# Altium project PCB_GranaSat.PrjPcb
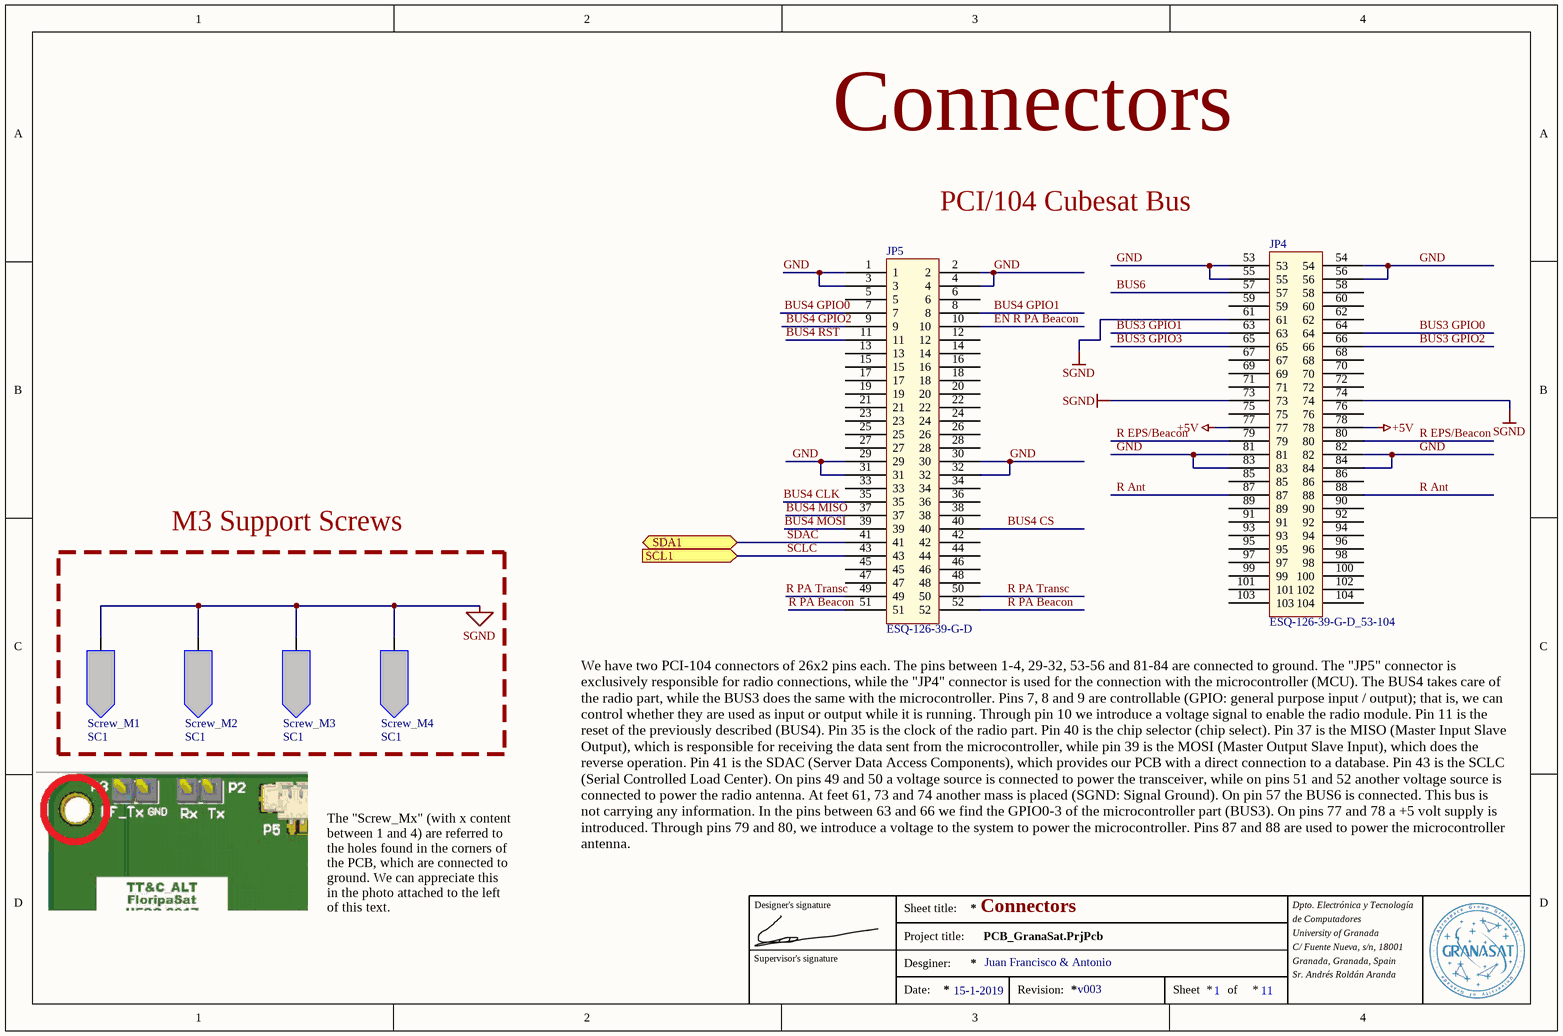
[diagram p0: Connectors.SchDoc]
11 sheets, 61 parts. Net scope: hierarchical (ports join the sheet entries above them; power ports are global).
Board files: PCBGranaSat.PcbDoc, PCBGSat.PCBdoc, PCB1.PcbDoc
Sheets:
  Connectors.SchDoc
  Interface.SchDoc
  Modules.SchDoc
  BeaconMCU.SchDoc
  BeaconMCU_Explained.SchDoc
  DecouplingCapacitors.SchDoc
  PullupResistors.SchDoc
  Reset.SchDoc
  LedsSystem.SchDoc
  Radio_RF4463F30_Beacon.SchDoc
  Radio_RF4463F30_Transceiver.SchDoc

## Sheet Connectors.SchDoc
size A4

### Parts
JP4  ESQ-126-39-G-D_53-104  [ESQ-126-39-G-D_53_104]
JP5  ESQ-126-39-G-D  [ESQ-126-39-G-D]
Screw_M1  SC1  [Screw_M3]
Screw_M2  SC1  [Screw_M3]
Screw_M3  SC1  [Screw_M3]
Screw_M4  SC1  [Screw_M3]

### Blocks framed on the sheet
M3 Support Screws: Screw_M1-Screw_M4

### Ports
SCL1 (in), SDA1 (bidir)

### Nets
+5V: JP4.77 JP4.78
SGND: JP4.61 JP4.73 JP4.74 Screw_M1.1 Screw_M2.1 Screw_M3.1 Screw_M4.1
BUS3 GPIO0: JP4.64
BUS3 GPIO1: JP4.63
BUS3 GPIO2: JP4.66
BUS3 GPIO3: JP4.65
BUS4 CLK: JP5.35
BUS4 CS: JP5.40
BUS4 GPIO0: JP5.7
BUS4 GPIO1: JP5.8
BUS4 GPIO2: JP5.9
BUS4 MISO: JP5.37
BUS4 MOSI: JP5.39
BUS4 RST: JP5.11
BUS6: JP4.57
EN R PA Beacon: JP5.10
GND: JP4.53 JP4.54 JP4.55 JP4.56 JP4.81 JP4.82 JP4.83 JP4.84 JP5.1 JP5.2 JP5.3 JP5.4 JP5.29 JP5.30 JP5.31 JP5.32
R Ant: JP4.87 JP4.88
R EPS/Beacon: JP4.79 JP4.80
R PA Beacon: JP5.51 JP5.52
R PA Transc: JP5.49 JP5.50
SCLC: JP5.43 ; port SCL1
SDAC: JP5.41 ; port SDA1

Not connected (* = marked no-connect by the designer): JP4 58 59 60 62 67 68 69 70 71 72 75 76 85 86 89 90 91 92 93 94 95 96 97 98 99 100 101 102 103 104; JP5 5 6 12 13 14 15 16 17 18 19 20 21 22 23 24 25 26 27 28 33 34 36 38 42 44 45 46 47 48

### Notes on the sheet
- Connectors
- PCI/104 Cubesat Bus
- We have two PCI-104 connectors of 26x2 pins each. The pins between 1-4, 29-32, 53-56 and 81-84 are connected to ground. The "JP5" connector is exclusively responsible for radio connections, while the "JP4" connector is used for the connection with the microcontroller (MCU). The BUS4 takes care of the radio part, while the BUS3 does the same with the microcontroller. Pins 7, 8 and 9 are controllable (GPIO: general purpose input / output); that is, we can control whether they are used as input or output while it is running. Through pin 10 we introduce a voltage signal to enable the radio module. Pin 11 is the reset of the previously described (BUS4). Pin 35 is the clock of the radio part. Pin 40 is the chip selector (chip select). Pin 37 is the MISO (Master Input Slave Output), which is responsible for receiving the data sent from the microcontroller, while pin 39 is the MOSI (Master Output Slave Input), which does the reverse operation. Pin 41 is the SDAC (Server Data Access Components), which provides our PCB with a direct connection to a database. Pin 43 is the SCLC (Serial Controlled Load Center). On pins 49 and 50 a voltage source is connected to power the transceiver, while on pins 51 and 52 another voltage source is connected to power the radio antenna. At feet 61, 73 and 74 another mass is placed (SGND: Signal Ground). On pin 57 the BUS6 is connected. This bus is not carrying any information. In the pins between 63 and 66 we find the GPIO0-3 of the microcontroller part (BUS3). On pins 77 and 78 a +5 volt supply is introduced. Through pins 79 and 80, we introduce a voltage to the system to power the microcontroller. Pins 87 and 88 are used to power the microcontroller antenna.
- The "Screw_Mx" (with x content between 1 and 4) are referred to the holes found in the corners of the PCB, which are connected to ground. We can appreciate this in the photo attached to the left of this text.
- Designer's signature
- Sheet title:
- Dpto. Electrónica y Tecnología
- de Computadores
- Supervisor's signature
- Project title:
- Desginer:
- Juan Francisco & Antonio
- University of Granada
- C/ Fuente Nueva, s/n, 18001
- Granada, Granada, Spain
- Sr. Andrés Roldán Aranda
- Date:
- 15-1-2019
- Revision:
- v003
- Sheet
- 1
- of
- 11

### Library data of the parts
JP4 = ESQ-126-39-G-D_53-104: Cubesat Header Connector; Shop: es.rs-online.com; Localización: Último cajón cajonera blanca entre Pablo y Luis; Reference: 254-6132
JP5 = ESQ-126-39-G-D: Cubesat Header Connector; Shop: es.rs-online.com; Localización: Último cajón cajonera blanca entre Pablo y Luis; Reference: 254-6132
Screw_M1-Screw_M4 = Screw_M3: Main CubeSAT bus

## Sheet Interface.SchDoc
size A4
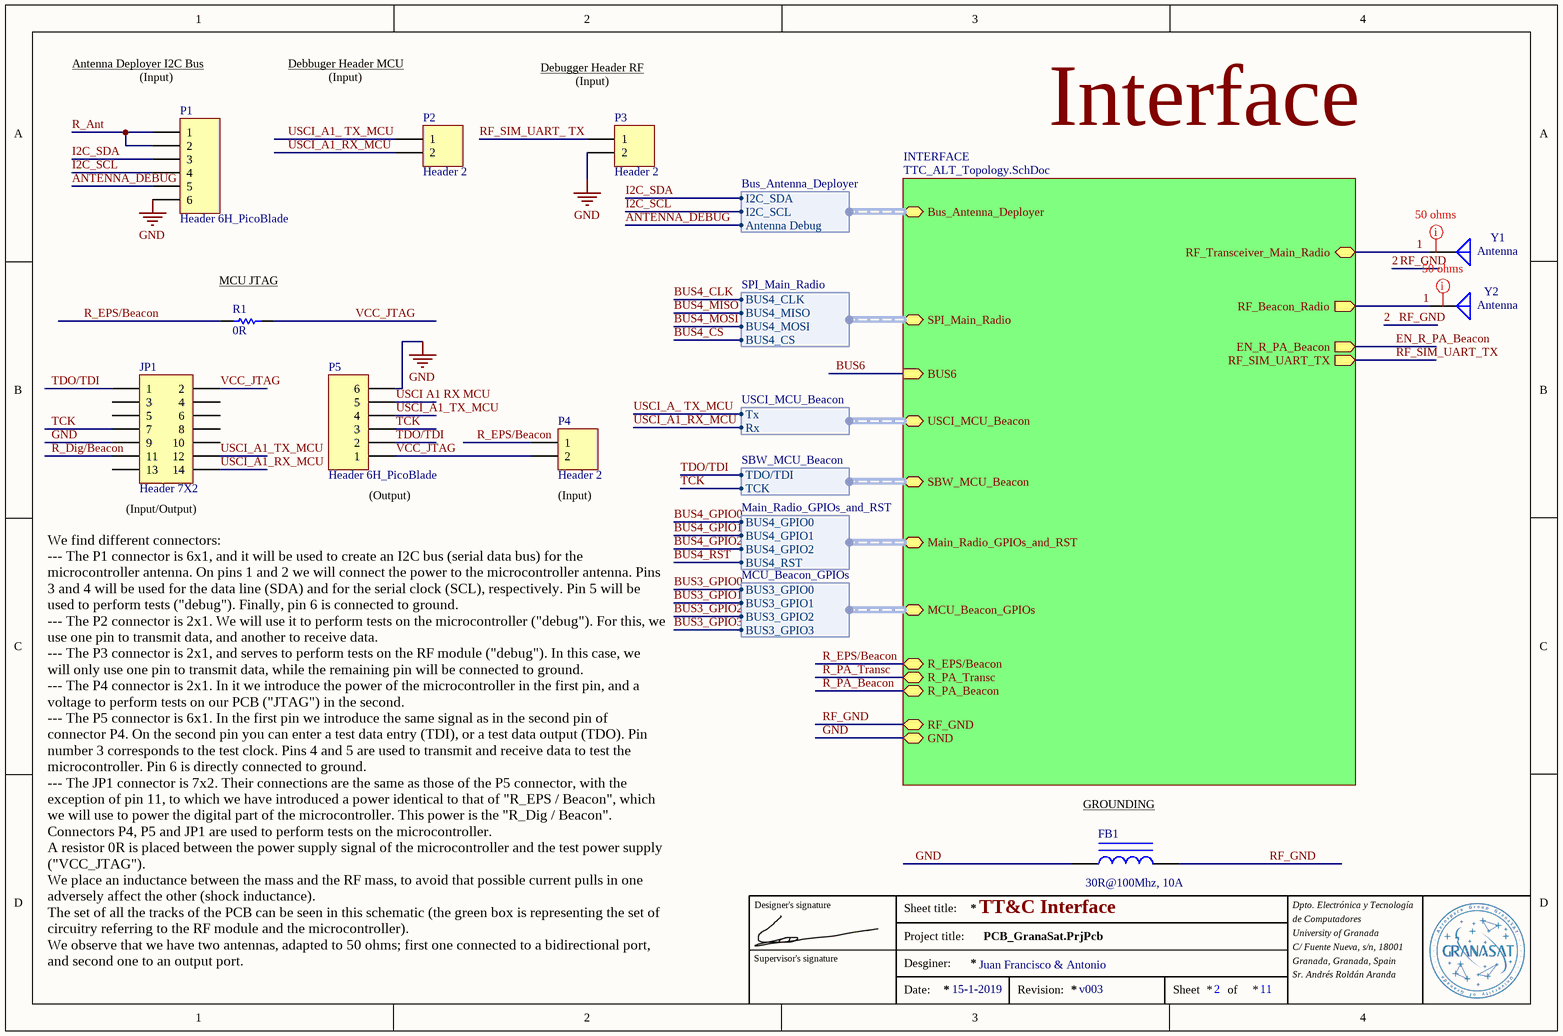
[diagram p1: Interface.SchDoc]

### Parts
FB1  value 30R@100Mhz, 10A  [INDC3216]
JP1  Header 7X2  [HDR2X7]
P1  Header 6H_PicoBlade  [HDR1X6H]
P2  Header 2  [HDR1X2]
P3  Header 2  [HDR1X2]
P4  Header 2  [HDR1X2]
P5  Header 6H_PicoBlade  [HDR1X6H]
R1  0R  [R]
Y1  Antenna  [PIN1]
Y2  Antenna  [PIN1]

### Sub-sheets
INTERFACE = TTC_ALT_Topology.SchDoc (file not in this document): RF_Transceiver_Main_Radio, RF_Beacon_Radio (out), EN_R_PA_Beacon (out), RF_SIM_UART_TX (out), Bus_Antenna_Deployer (harness Bus_Antenna_Deployer), SPI_Main_Radio (harness SPI_Main_Radio), BUS6 (in), Main_Radio_GPIOs_and_RST (harness Main_Radio_GPIOs_and_RST), USCI_MCU_Beacon (harness USCI_MCU_Beacon), MCU_Beacon_GPIOs (harness MCU_Beacon_GPIOs), R_EPS/Beacon, R_PA_Transc, R_PA_Beacon, RF_GND, GND, SBW_MCU_Beacon (harness SBW_MCU_Beacon)

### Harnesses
Bus_Antenna_Deployer: I2C_SDA, I2C_SCL, Antenna Debug
SPI_Main_Radio: BUS4_CLK, BUS4_MISO, BUS4_MOSI, BUS4_CS
SBW_MCU_Beacon: TDO/TDI, TCK
Main_Radio_GPIOs_and_RST: BUS4_GPIO0, BUS4_GPIO1, BUS4_GPIO2, BUS4_RST
MCU_Beacon_GPIOs: BUS3_GPIO0, BUS3_GPIO1, BUS3_GPIO2, BUS3_GPIO3
USCI_MCU_Beacon: Tx, Rx

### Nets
GND: FB1.1 JP1.9 P1.6 P3.2 P5.6 ; sheet INTERFACE/GND
1: Y1.1(A) Y2.1(A) ; sheet INTERFACE/RF_Transceiver_Main_Radio, sheet INTERFACE/RF_Beacon_Radio
2: FB1.2 ; sheet INTERFACE/RF_GND  [also labelled RF_GND]
ANTENNA_DEBUG: P1.5 ; sheet INTERFACE/Bus_Antenna_Deployer.Antenna Debug
I2C_SCL: P1.4 ; sheet INTERFACE/Bus_Antenna_Deployer.I2C_SCL
I2C_SDA: P1.3 ; sheet INTERFACE/Bus_Antenna_Deployer.I2C_SDA
R_Ant: P1.1 P1.2
R_Dig/Beacon: JP1.11
R_EPS/Beacon: P4.1 R1.1 ; sheet INTERFACE/R_EPS/Beacon
RF_SIM_UART_ TX: P3.1
TCK: JP1.7 P5.3 ; sheet INTERFACE/SBW_MCU_Beacon.TCK
TDO/TDI: JP1.1 P5.2 ; sheet INTERFACE/SBW_MCU_Beacon.TDO/TDI
USCI A1 RX MCU: P5.5
USCI_A1_ TX_MCU: P2.1
USCI_A1_RX_MCU: JP1.14 P2.2 ; sheet INTERFACE/USCI_MCU_Beacon.Rx
USCI_A1_TX_MCU: JP1.12 P5.4
VCC_JTAG: JP1.2 P4.2 P5.1 R1.2

Not connected (* = marked no-connect by the designer): JP1 3 4 5 6 8 10 13

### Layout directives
mark named 50 ohms: (no net found under the mark)

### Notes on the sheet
- Antenna Deployer I2C Bus
- (near P1) (Input)
- Debbuger Header MCU
- (Input)
- Debugger Header RF
- (near P3) (Input)
- Interface
- (near R1) MCU JTAG
- (near JP1) (Input/Output)
- (near P5) (Output)
- (near P4) (Input)
- (near FB1) GROUNDING
- Designer's signature
- Sheet title:
- (near FB1) TT&C Interface
- Dpto. Electrónica y Tecnología
- de Computadores
- We find different connectors:
  --- The P1 connector is 6x1, and it will be used to create an I2C bus (serial data bus) for the microcontroller antenna. On pins 1 and 2 we will connect the power to the microcontroller antenna. Pins 3 and 4 will be used for the data line (SDA) and for the serial clock (SCL), respectively. Pin 5 will be used to perform tests ("debug"). Finally, pin 6 is connected to ground.
  --- The P2 connector is 2x1. We will use it to perform tests on the microcontroller ("debug"). For this, we use one pin to transmit data, and another to receive data.
  --- The P3 connector is 2x1, and serves to perform tests on the RF module ("debug"). In this case, we will only use one pin to transmit data, while the remaining pin will be connected to ground.
  --- The P4 connector is 2x1. In it we introduce the power of the microcontroller in the first pin, and a voltage to perform tests on our PCB ("JTAG") in the second.
  --- The P5 connector is 6x1. In the first pin we introduce the same signal as in the second pin of connector P4. On the second pin you can enter a test data entry (TDI), or a test data output (TDO). Pin number 3 corresponds to the test clock. Pins 4 and 5 are used to transmit and receive data to test the microcontroller. Pin 6 is directly connected to ground.
  --- The JP1 connector is 7x2. Their connections are the same as those of the P5 connector, with the exception of pin 11, to which we have introduced a power identical to that of "R_EPS / Beacon", which we will use to power the digital part of the microcontroller. This power is the "R_Dig / Beacon".
  Connectors P4, P5 and JP1 are used to perform tests on the microcontroller.
  A resistor 0R is placed between the power supply signal of the microcontroller and the test power supply ("VCC_JTAG").
  We place an inductance between the mass and the RF mass, to avoid that possible current pulls in one adversely affect the other (shock inductance).
  The set of all the tracks of the PCB can be seen in this schematic (the green box is representing the set of circuitry referring to the RF module and the microcontroller).
  We observe that we have two antennas, adapted to 50 ohms; first one connected to a bidirectional port, and second one to an output port.
- Supervisor's signature
- Project title:
- Desginer:
- Juan Francisco & Antonio
- University of Granada
- C/ Fuente Nueva, s/n, 18001
- Granada, Granada, Spain
- Sr. Andrés Roldán Aranda
- Date:
- 15-1-2019
- Revision:
- v003
- Sheet
- 2
- of
- 11

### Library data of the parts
FB1 = Inductor Iron: Magnetic-Core Inductor
JP1 = Header 7X2: Header, 7-Pin, Dual row
P1 = Header 6H: Header, 6-Pin, Right Angle
P2-P4 = Header 2: Header, 2-Pin
P5 = Header 6H: Header, 6-Pin, Left Angle
R1 = Res1: Resistor
Y1 Y2 = Antenna: Generic Antenna

## Sheet Modules.SchDoc
size A4
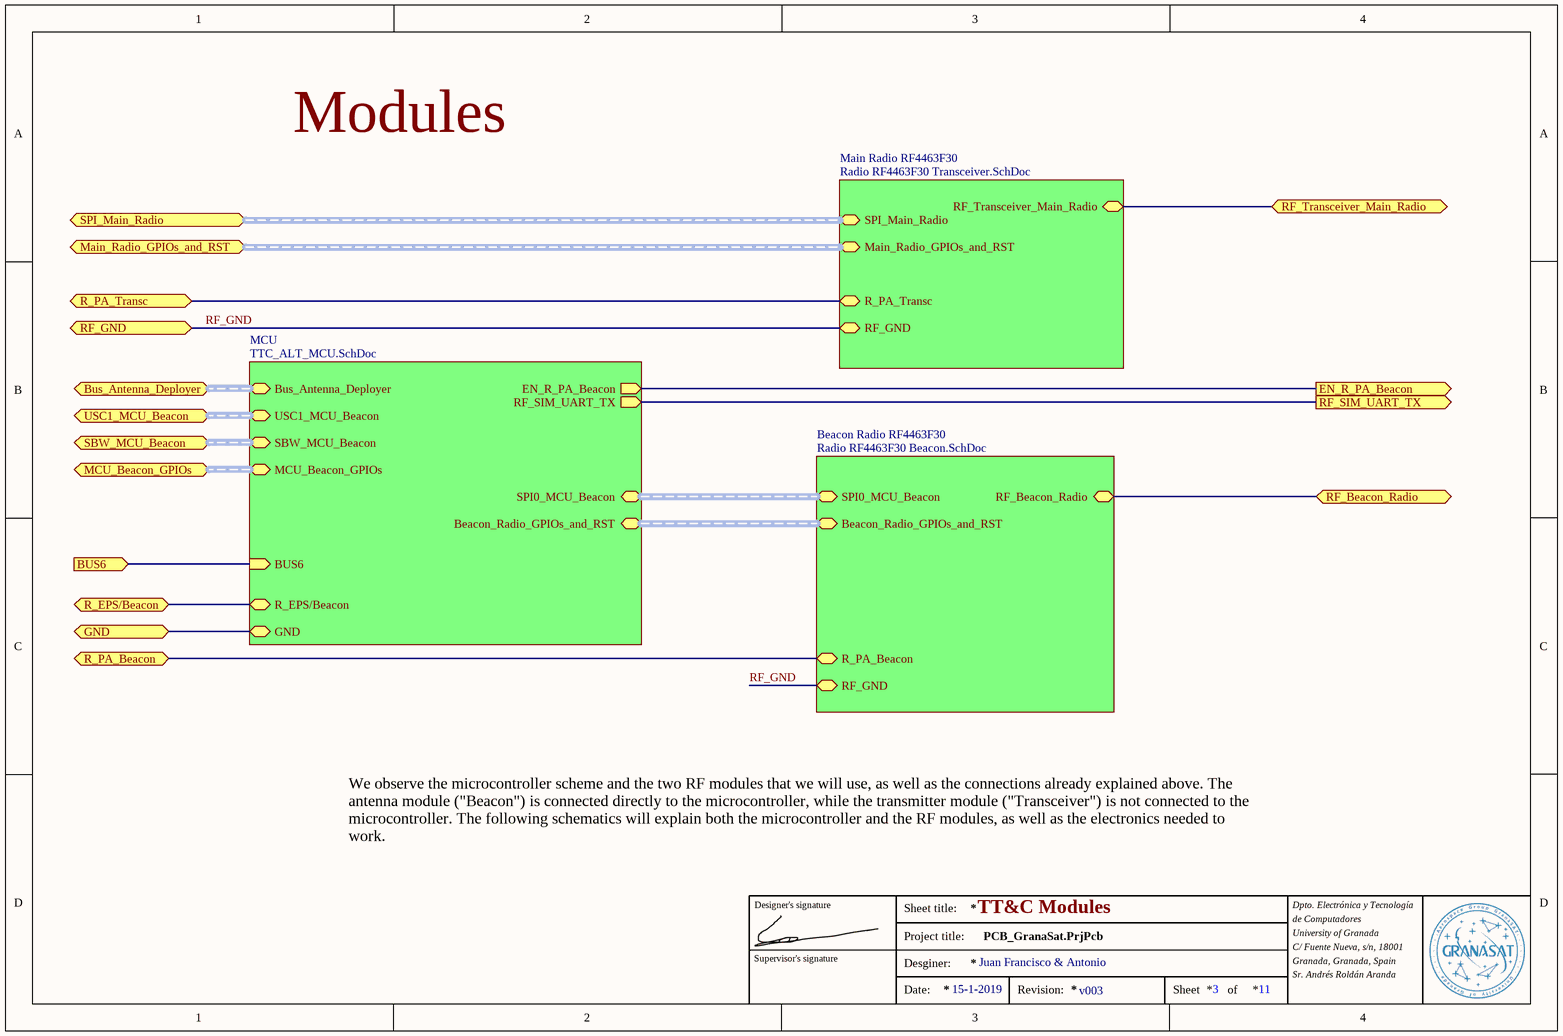
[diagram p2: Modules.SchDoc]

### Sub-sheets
Beacon Radio RF4463F30 = Radio RF4463F30 Beacon.SchDoc (file not in this document): SPI0_MCU_Beacon, Beacon_Radio_GPIOs_and_RST, R_PA_Beacon, RF_GND, RF_Beacon_Radio
Main Radio RF4463F30 = Radio RF4463F30 Transceiver.SchDoc (file not in this document): RF_Transceiver_Main_Radio, R_PA_Transc, RF_GND, SPI_Main_Radio, Main_Radio_GPIOs_and_RST
MCU = TTC_ALT_MCU.SchDoc (file not in this document): BUS6, R_EPS/Beacon, GND, SBW_MCU_Beacon, Bus_Antenna_Deployer, USC1_MCU_Beacon, MCU_Beacon_GPIOs, EN_R_PA_Beacon, RF_SIM_UART_TX, SPI0_MCU_Beacon, Beacon_Radio_GPIOs_and_RST

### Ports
BUS6, Bus_Antenna_Deployer, EN_R_PA_Beacon, GND, Main_Radio_GPIOs_and_RST, MCU_Beacon_GPIOs, R_EPS/Beacon, R_PA_Beacon, R_PA_Transc, RF_Beacon_Radio, RF_GND, RF_SIM_UART_TX, RF_Transceiver_Main_Radio, SBW_MCU_Beacon, SPI_Main_Radio, USC1_MCU_Beacon

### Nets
RF_GND: port RF_GND, sheet Main Radio RF4463F30/RF_GND, sheet Beacon Radio RF4463F30/RF_GND
(unnamed): port R_PA_Transc, sheet Main Radio RF4463F30/R_PA_Transc
(unnamed): port RF_Transceiver_Main_Radio, sheet Main Radio RF4463F30/RF_Transceiver_Main_Radio  [a separate net that carries the same name]
(unnamed): port BUS6, sheet MCU/BUS6  [a separate net that carries the same name]
(unnamed): port R_EPS/Beacon, sheet MCU/R_EPS/Beacon  [a separate net that carries the same name]
(unnamed): port GND, sheet MCU/GND  [a separate net that carries the same name]
(unnamed): port EN_R_PA_Beacon, sheet MCU/EN_R_PA_Beacon  [a separate net that carries the same name]
(unnamed): port RF_SIM_UART_TX, sheet MCU/RF_SIM_UART_TX  [a separate net that carries the same name]
(unnamed): port R_PA_Beacon, sheet Beacon Radio RF4463F30/R_PA_Beacon  [a separate net that carries the same name]
(unnamed): port RF_Beacon_Radio, sheet Beacon Radio RF4463F30/RF_Beacon_Radio  [a separate net that carries the same name]

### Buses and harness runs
harness port Bus_Antenna_Deployer = sheet MCU/Bus_Antenna_Deployer
harness port Main_Radio_GPIOs_and_RST = sheet Main Radio RF4463F30/Main_Radio_GPIOs_and_RST
harness port MCU_Beacon_GPIOs = sheet MCU/MCU_Beacon_GPIOs
harness port SBW_MCU_Beacon = sheet MCU/SBW_MCU_Beacon
harness port SPI_Main_Radio = sheet Main Radio RF4463F30/SPI_Main_Radio
harness port USC1_MCU_Beacon = sheet MCU/USC1_MCU_Beacon
harness sheet Beacon Radio RF4463F30/Beacon_Radio_GPIOs_and_RST = sheet MCU/Beacon_Radio_GPIOs_and_RST
harness sheet Beacon Radio RF4463F30/SPI0_MCU_Beacon = sheet MCU/SPI0_MCU_Beacon

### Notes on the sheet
- Modules
- Designer's signature
- Sheet title:
- TT&C Modules
- Dpto. Electrónica y Tecnología
- de Computadores
- We observe the microcontroller scheme and the two RF modules that we will use, as well as the connections already explained above. The antenna module ("Beacon") is connected directly to the microcontroller, while the transmitter module ("Transceiver") is not connected to the microcontroller. The following schematics will explain both the microcontroller and the RF modules, as well as the electronics needed to work.
- Supervisor's signature
- Project title:
- Desginer:
- Juan Francisco & Antonio
- University of Granada
- C/ Fuente Nueva, s/n, 18001
- Granada, Granada, Spain
- Sr. Andrés Roldán Aranda
- Date:
- 15-1-2019
- Revision:
- v003
- Sheet
- 3
- of
- 11

## Sheet BeaconMCU.SchDoc
size A4
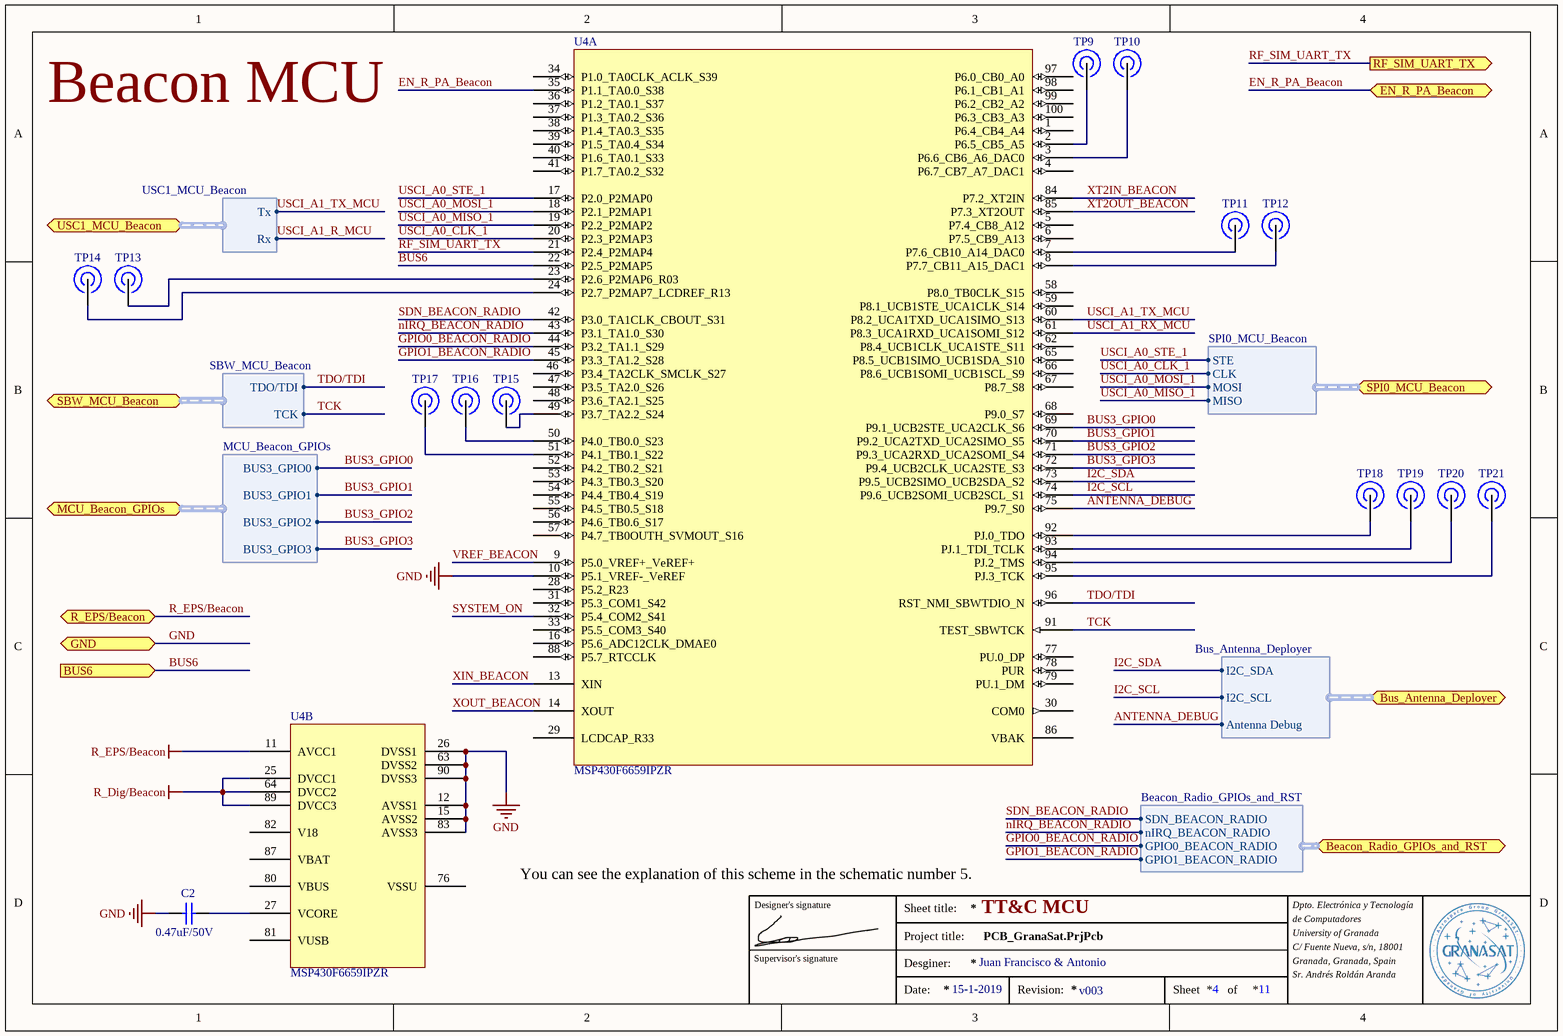
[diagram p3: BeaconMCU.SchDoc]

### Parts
C2  value 0.47uF/50V  [C0.47u]
TP9  TestPoint  [TESTPOINT_2x2mm]  (value not drawn)
TP10  TestPoint  [TESTPOINT_2x2mm]  (value not drawn)
TP11  TestPoint  [TESTPOINT_2x2mm]  (value not drawn)
TP12  TestPoint  [TESTPOINT_2x2mm]  (value not drawn)
TP13  TestPoint  [TESTPOINT_2x2mm]  (value not drawn)
TP14  TestPoint  [TESTPOINT_2x2mm]  (value not drawn)
TP15  TestPoint  [TESTPOINT_2x2mm]  (value not drawn)
TP16  TestPoint  [TESTPOINT_2x2mm]  (value not drawn)
TP17  TestPoint  [TESTPOINT_2x2mm]  (value not drawn)
TP18  TestPoint  [TESTPOINT_2x2mm]  (value not drawn)
TP19  TestPoint  [TESTPOINT_2x2mm]  (value not drawn)
TP20  TestPoint  [TESTPOINT_2x2mm]  (value not drawn)
TP21  TestPoint  [TESTPOINT_2x2mm]  (value not drawn)
U4A  MSP430F6659IPZR  [MSP430F6659IPZR]
U4B  MSP430F6659IPZR  [MSP430F6659IPZR]

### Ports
Beacon_Radio_GPIOs_and_RST (harness Beacon_Radio_GPIOs_and_RST), BUS6 (in), Bus_Antenna_Deployer (harness Bus_Antenna_Deployer), EN_R_PA_Beacon, GND, MCU_Beacon_GPIOs (harness MCU_Beacon_GPIOs), R_EPS/Beacon (bidir), RF_SIM_UART_TX (out), SBW_MCU_Beacon (harness SBW_MCU_Beacon), SPI0_MCU_Beacon (harness SPI0_MCU_Beacon), USC1_MCU_Beacon (harness USC1_MCU_Beacon)

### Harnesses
USC1_MCU_Beacon: Rx, Tx
SBW_MCU_Beacon: TCK, TDO/TDI
MCU_Beacon_GPIOs: BUS3_GPIO0, BUS3_GPIO1, BUS3_GPIO2, BUS3_GPIO3
Bus_Antenna_Deployer: I2C_SDA, I2C_SCL, Antenna Debug
Beacon_Radio_GPIOs_and_RST: SDN_BEACON_RADIO, nIRQ_BEACON_RADIO, GPIO0_BEACON_RADIO, GPIO1_BEACON_RADIO
SPI0_MCU_Beacon: STE, CLK, MOSI, MISO

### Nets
GND: C2.1 U4A.10(P5.1_VREF-_VeREF) U4B.12(AVSS1) U4B.15(AVSS2) U4B.26(DVSS1) U4B.63(DVSS2) U4B.83(AVSS3) U4B.90(DVSS3) ; port GND
R_Dig/Beacon: U4B.25(DVCC1) U4B.64(DVCC2) U4B.89(DVCC3)
R_EPS/Beacon: U4B.11(AVCC1) ; port R_EPS/Beacon
ANTENNA_DEBUG: U4A.75(P9.7_S0) ; port Bus_Antenna_Deployer.Antenna Debug
BUS3_GPIO0: U4A.69(P9.1_UCB2STE_UCA2CLK_S6) ; port MCU_Beacon_GPIOs.BUS3_GPIO0
BUS3_GPIO1: U4A.70(P9.2_UCA2TXD_UCA2SIMO_S5) ; port MCU_Beacon_GPIOs.BUS3_GPIO1
BUS3_GPIO2: U4A.71(P9.3_UCA2RXD_UCA2SOMI_S4) ; port MCU_Beacon_GPIOs.BUS3_GPIO2
BUS3_GPIO3: U4A.72(P9.4_UCB2CLK_UCA2STE_S3) ; port MCU_Beacon_GPIOs.BUS3_GPIO3
BUS6: U4A.22(P2.5_P2MAP5) ; port BUS6
EN_R_PA_Beacon: U4A.35(P1.1_TA0.0_S38) ; port EN_R_PA_Beacon
GPIO0_BEACON_RADIO: U4A.44(P3.2_TA1.1_S29) ; port Beacon_Radio_GPIOs_and_RST.GPIO0_BEACON_RADIO
GPIO1_BEACON_RADIO: U4A.45(P3.3_TA1.2_S28) ; port Beacon_Radio_GPIOs_and_RST.GPIO1_BEACON_RADIO
I2C_SCL: U4A.74(P9.6_UCB2SOMI_UCB2SCL_S1) ; port Bus_Antenna_Deployer.I2C_SCL
I2C_SDA: U4A.73(P9.5_UCB2SIMO_UCB2SDA_S2) ; port Bus_Antenna_Deployer.I2C_SDA
nIRQ_BEACON_RADIO: U4A.43(P3.1_TA1.0_S30) ; port Beacon_Radio_GPIOs_and_RST.nIRQ_BEACON_RADIO
RF_SIM_UART_TX: U4A.21(P2.4_P2MAP4) ; port RF_SIM_UART_TX
SDN_BEACON_RADIO: U4A.42(P3.0_TA1CLK_CBOUT_S31) ; port Beacon_Radio_GPIOs_and_RST.SDN_BEACON_RADIO
SYSTEM_ON: U4A.32(P5.4_COM2_S41)
TCK: U4A.91(TEST_SBWTCK) ; port SBW_MCU_Beacon.TCK
TDO/TDI: U4A.96(RST_NMI_SBWTDIO_N) ; port SBW_MCU_Beacon.TDO/TDI
USCI_A0_CLK_1: U4A.20(P2.3_P2MAP3) ; port SPI0_MCU_Beacon.CLK
USCI_A0_MISO_1: U4A.19(P2.2_P2MAP2) ; port SPI0_MCU_Beacon.MISO
USCI_A0_MOSI_1: U4A.18(P2.1_P2MAP1) ; port SPI0_MCU_Beacon.MOSI
USCI_A0_STE_1: U4A.17(P2.0_P2MAP0) ; port SPI0_MCU_Beacon.STE
USCI_A1_RX_MCU: U4A.61(P8.3_UCA1RXD_UCA1SOMI_S12)
USCI_A1_TX_MCU: U4A.60(P8.2_UCA1TXD_UCA1SIMO_S13) ; port USC1_MCU_Beacon.Tx
VREF_BEACON: U4A.9(P5.0_VREF+_VeREF+)
XIN_BEACON: U4A.13(XIN)
XOUT_BEACON: U4A.14(XOUT)
XT2IN_BEACON: U4A.84(P7.2_XT2IN)
XT2OUT_BEACON: U4A.85(P7.3_XT2OUT)
NetC2_2: C2.2 U4B.27(VCORE)
NetTP9_1: TP9.1 U4A.2(P6.5_CB5_A5)
NetTP10_1: TP10.1 U4A.3(P6.6_CB6_A6_DAC0)
NetTP11_1: TP11.1 U4A.7(P7.6_CB10_A14_DAC0)
NetTP12_1: TP12.1 U4A.8(P7.7_CB11_A15_DAC1)
NetTP13_1: TP13.1 U4A.23(P2.6_P2MAP6_R03)
NetTP14_1: TP14.1 U4A.24(P2.7_P2MAP7_LCDREF_R13)
NetTP15_1: TP15.1 U4A.49(P3.7_TA2.2_S24)
NetTP16_1: TP16.1 U4A.50(P4.0_TB0.0_S23)
NetTP17_1: TP17.1 U4A.51(P4.1_TB0.1_S22)
NetTP18_1: TP18.1 U4A.92(PJ.0_TDO)
NetTP19_1: TP19.1 U4A.93(PJ.1_TDI_TCLK)
NetTP20_1: TP20.1 U4A.94(PJ.2_TMS)
NetTP21_1: TP21.1 U4A.95(PJ.3_TCK)

Not connected (* = marked no-connect by the designer): U4A 1(P6.4_CB4_A4) 4(P6.7_CB7_A7_DAC1) 5(P7.4_CB8_A12) 6(P7.5_CB9_A13) 16(P5.6_ADC12CLK_DMAE0) 28(P5.2_R23) 29(LCDCAP_R33) 30(COM0) 31(P5.3_COM1_S42) 33(P5.5_COM3_S40) 34(P1.0_TA0CLK_ACLK_S39) 36(P1.2_TA0.1_S37) 37(P1.3_TA0.2_S36) 38(P1.4_TA0.3_S35) 39(P1.5_TA0.4_S34) 40(P1.6_TA0.1_S33) 41(P1.7_TA0.2_S32) 46(P3.4_TA2CLK_SMCLK_S27) 47(P3.5_TA2.0_S26) 48(P3.6_TA2.1_S25) 52(P4.2_TB0.2_S21) 53(P4.3_TB0.3_S20) 54(P4.4_TB0.4_S19) 55(P4.5_TB0.5_S18) 56(P4.6_TB0.6_S17) 57(P4.7_TB0OUTH_SVMOUT_S16) 58(P8.0_TB0CLK_S15) 59(P8.1_UCB1STE_UCA1CLK_S14) 62(P8.4_UCB1CLK_UCA1STE_S11) 65(P8.5_UCB1SIMO_UCB1SDA_S10) 66(P8.6_UCB1SOMI_UCB1SCL_S9) 67(P8.7_S8) 68(P9.0_S7) 77(PU.0_DP) 78(PUR) 79(PU.1_DM) 86(VBAK) 88(P5.7_RTCCLK) 97(P6.0_CB0_A0) 98(P6.1_CB1_A1) 99(P6.2_CB2_A2) 100(P6.3_CB3_A3); U4B 76(VSSU) 80(VBUS) 81(VUSB) 82(V18) 87(VBAT)

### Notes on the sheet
- Beacon MCU
- Designer's signature
- Sheet title:
- TT&C MCU
- Dpto. Electrónica y Tecnología
- de Computadores
- You can see the explanation of this scheme in the schematic number 5.
- Supervisor's signature
- Project title:
- Desginer:
- Juan Francisco & Antonio
- University of Granada
- C/ Fuente Nueva, s/n, 18001
- Granada, Granada, Spain
- Sr. Andrés Roldán Aranda
- Date:
- 15-1-2019
- Revision:
- v003
- Sheet
- 4
- of
- 11

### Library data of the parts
C2 = Cap Semi: Capacitor (Semiconductor SIM Model)
TP9-TP21 = TestPoint: Punto de prueba de 3x3mm; pin to pad: 1>TP; PCB DECAL: TestPoint XxXmm

## Sheet BeaconMCU_Explained.SchDoc
size A4
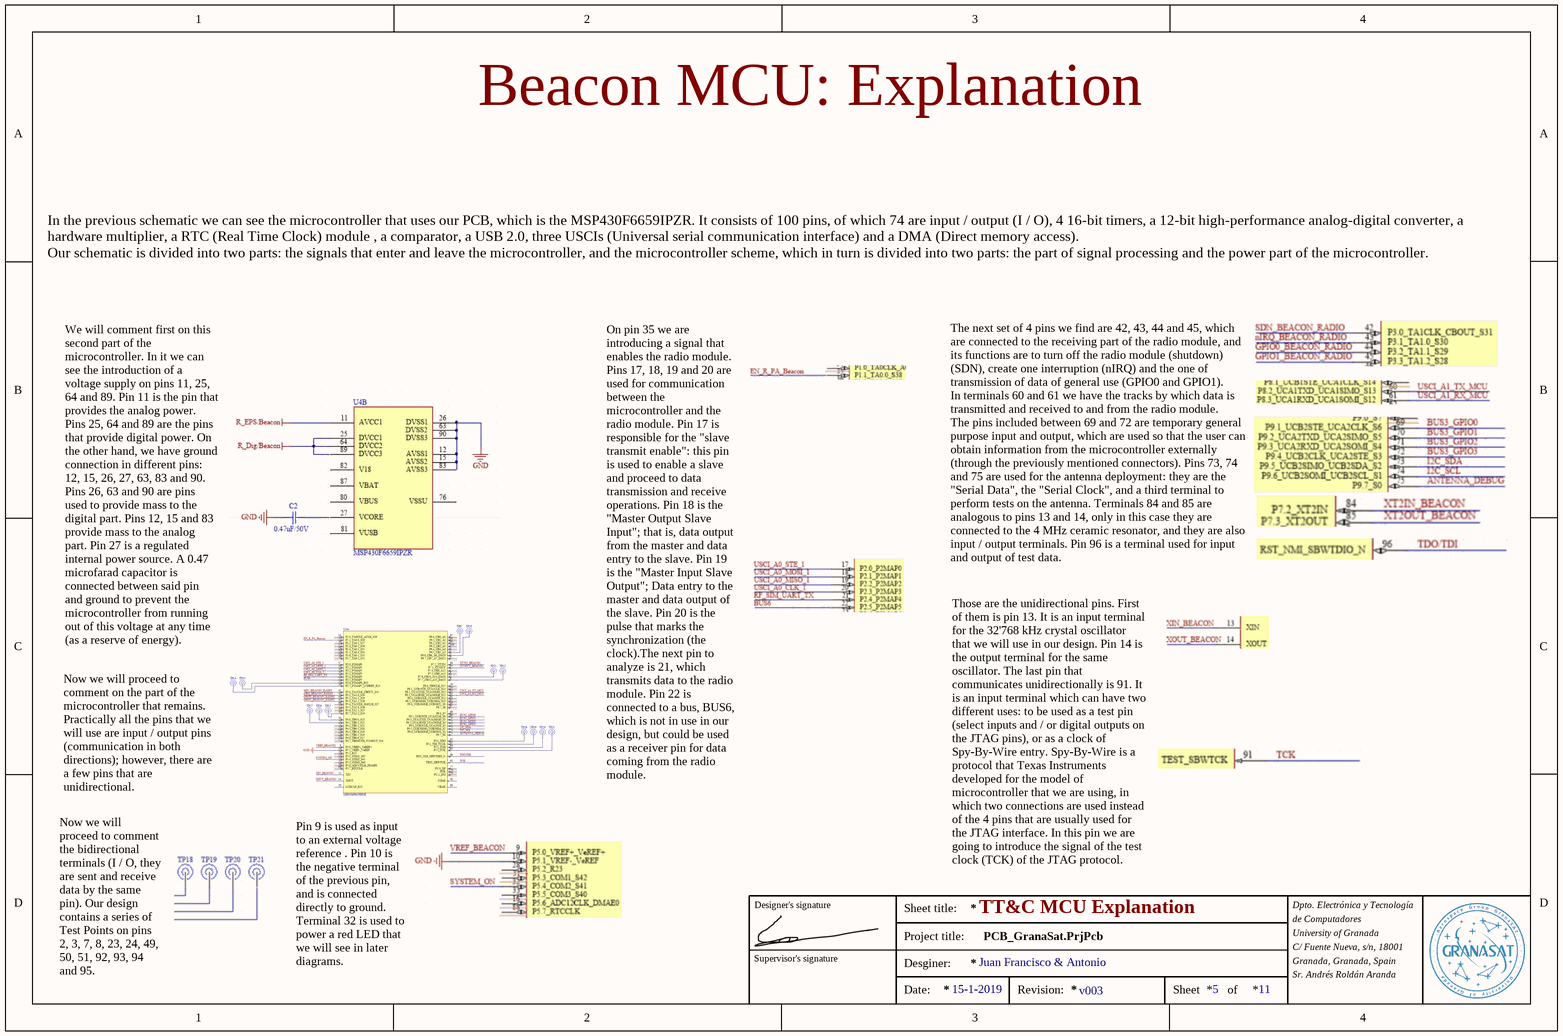
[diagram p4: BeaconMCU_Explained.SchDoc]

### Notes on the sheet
- Beacon MCU: Explanation
- In the previous schematic we can see the microcontroller that uses our PCB, which is the MSP430F6659IPZR. It consists of 100 pins, of which 74 are input / output (I / O), 4 16-bit timers, a 12-bit high-performance analog-digital converter, a hardware multiplier, a RTC (Real Time Clock) module , a comparator, a USB 2.0, three USCIs (Universal serial communication interface) and a DMA (Direct memory access).
  Our schematic is divided into two parts: the signals that enter and leave the microcontroller, and the microcontroller scheme, which in turn is divided into two parts: the part of signal processing and the power part of the microcontroller.
- The next set of 4 pins we find are 42, 43, 44 and 45, which are connected to the receiving part of the radio module, and its functions are to turn off the radio module (shutdown) (SDN), create one interruption (nIRQ) and the one of transmission of data of general use (GPIO0 and GPIO1).
  In terminals 60 and 61 we have the tracks by which data is transmitted and received to and from the radio module.
  The pins included between 69 and 72 are temporary general purpose input and output, which are used so that the user can obtain information from the microcontroller externally (through the previously mentioned connectors). Pins 73, 74 and 75 are used for the antenna deployment: they are the "Serial Data", the "Serial Clock", and a third terminal to perform tests on the antenna. Terminals 84 and 85 are analogous to pins 13 and 14, only in this case they are connected to the 4 MHz ceramic resonator, and they are also input / output terminals. Pin 96 is a terminal used for input and output of test data.
- We will comment first on this second part of the microcontroller. In it we can see the introduction of a voltage supply on pins 11, 25, 64 and 89. Pin 11 is the pin that provides the analog power. Pins 25, 64 and 89 are the pins that provide digital power. On the other hand, we have ground connection in different pins: 12, 15, 26, 27, 63, 83 and 90. Pins 26, 63 and 90 are pins used to provide mass to the digital part. Pins 12, 15 and 83 provide mass to the analog part. Pin 27 is a regulated internal power source. A 0.47 microfarad capacitor is connected between said pin and ground to prevent the microcontroller from running out of this voltage at any time (as a reserve of energy).
- On pin 35 we are introducing a signal that enables the radio module. Pins 17, 18, 19 and 20 are used for communication between the microcontroller and the radio module. Pin 17 is responsible for the "slave transmit enable": this pin is used to enable a slave and proceed to data transmission and receive operations. Pin 18 is the "Master Output Slave Input"; that is, data output from the master and data entry to the slave. Pin 19 is the "Master Input Slave Output"; Data entry to the master and data output of the slave. Pin 20 is the pulse that marks the synchronization (the clock).The next pin to analyze is 21, which transmits data to the radio module. Pin 22 is connected to a bus, BUS6, which is not in use in our design, but could be used as a receiver pin for data coming from the radio module.
- Now we will proceed to comment on the part of the microcontroller that remains. Practically all the pins that we will use are input / output pins (communication in both directions); however, there are a few pins that are unidirectional.
- Designer's signature
- Sheet title:
- Those are the unidirectional pins. First of them is pin 13. It is an input terminal for the 32'768 kHz crystal oscillator that we will use in our design. Pin 14 is the output terminal for the same oscillator. The last pin that communicates unidirectionally is 91. It is an input terminal which can have two different uses: to be used as a test pin (select inputs and / or digital outputs on the JTAG pins), or as a clock of Spy-By-Wire entry. Spy-By-Wire is a protocol that Texas Instruments developed for the model of microcontroller that we are using, in which two connections are used instead of the 4 pins that are usually used for the JTAG interface. In this pin we are going to introduce the signal of the test clock (TCK) of the JTAG protocol.
- TT&C MCU Explanation
- Dpto. Electrónica y Tecnología
- de Computadores
- Now we will proceed to comment the bidirectional terminals (I / O, they are sent and receive data by the same pin). Our design contains a series of Test Points on pins 2, 3, 7, 8, 23, 24, 49, 50, 51, 92, 93, 94 and 95.
- Pin 9 is used as input to an external voltage reference . Pin 10 is the negative terminal of the previous pin, and is connected directly to ground. Terminal 32 is used to power a red LED that we will see in later diagrams.
- Supervisor's signature
- Project title:
- Desginer:
- Juan Francisco & Antonio
- University of Granada
- C/ Fuente Nueva, s/n, 18001
- Granada, Granada, Spain
- Sr. Andrés Roldán Aranda
- Date:
- 15-1-2019
- Revision:
- v003
- Sheet
- 5
- of
- 11

## Sheet DecouplingCapacitors.SchDoc
size A4
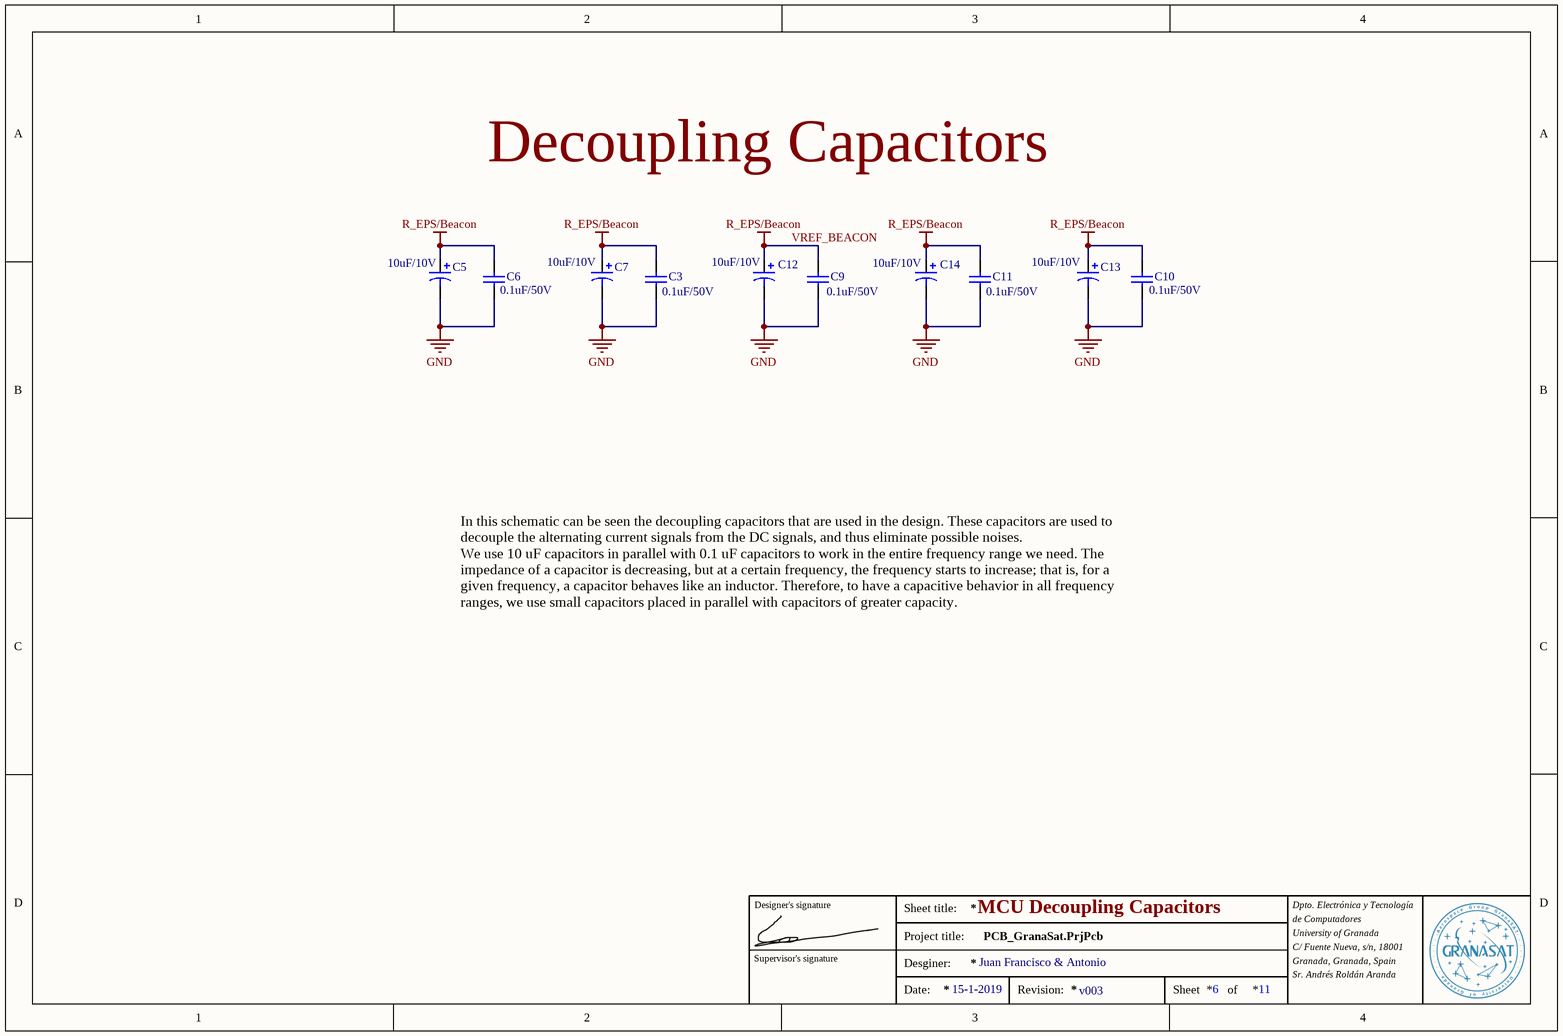
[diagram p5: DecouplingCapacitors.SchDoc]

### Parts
C3  value 0.1uF/50V  [CN]
C5  value 10uF/10V  [C10u]
C6  value 0.1uF/50V  [CN]
C7  value 10uF/10V  [C10u]
C9  value 0.1uF/50V  [CN]
C10  value 0.1uF/50V  [CN]
C11  value 0.1uF/50V  [CN]
C12  value 10uF/10V  [C10u]
C13  value 10uF/10V  [C10u]
C14  value 10uF/10V  [C10u]

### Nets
GND: C3.2 C5.2 C6.2 C7.2 C9.2 C10.2 C11.2 C12.2 C13.2 C14.2
R_EPS/Beacon: C3.1 C5.1 C6.1 C7.1 C9.1 C10.1 C11.1 C12.1 C13.1 C14.1  [also labelled VREF_BEACON]

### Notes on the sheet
- Decoupling Capacitors
- In this schematic can be seen the decoupling capacitors that are used in the design. These capacitors are used to decouple the alternating current signals from the DC signals, and thus eliminate possible noises.
  We use 10 uF capacitors in parallel with 0.1 uF capacitors to work in the entire frequency range we need. The impedance of a capacitor is decreasing, but at a certain frequency, the frequency starts to increase; that is, for a given frequency, a capacitor behaves like an inductor. Therefore, to have a capacitive behavior in all frequency ranges, we use small capacitors placed in parallel with capacitors of greater capacity.
- Designer's signature
- Sheet title:
- MCU Decoupling Capacitors
- Dpto. Electrónica y Tecnología
- de Computadores
- Supervisor's signature
- Project title:
- Desginer:
- Juan Francisco & Antonio
- University of Granada
- C/ Fuente Nueva, s/n, 18001
- Granada, Granada, Spain
- Sr. Andrés Roldán Aranda
- Date:
- 15-1-2019
- Revision:
- v003
- Sheet
- 6
- of
- 11

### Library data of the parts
C3 C6 C9-C11 = Cap Semi: Capacitor (Semiconductor SIM Model)
C5 C7 C12-C14 = Cap Pol3: Polarized Capacitor (Surface Mount)

## Sheet PullupResistors.SchDoc
size A4
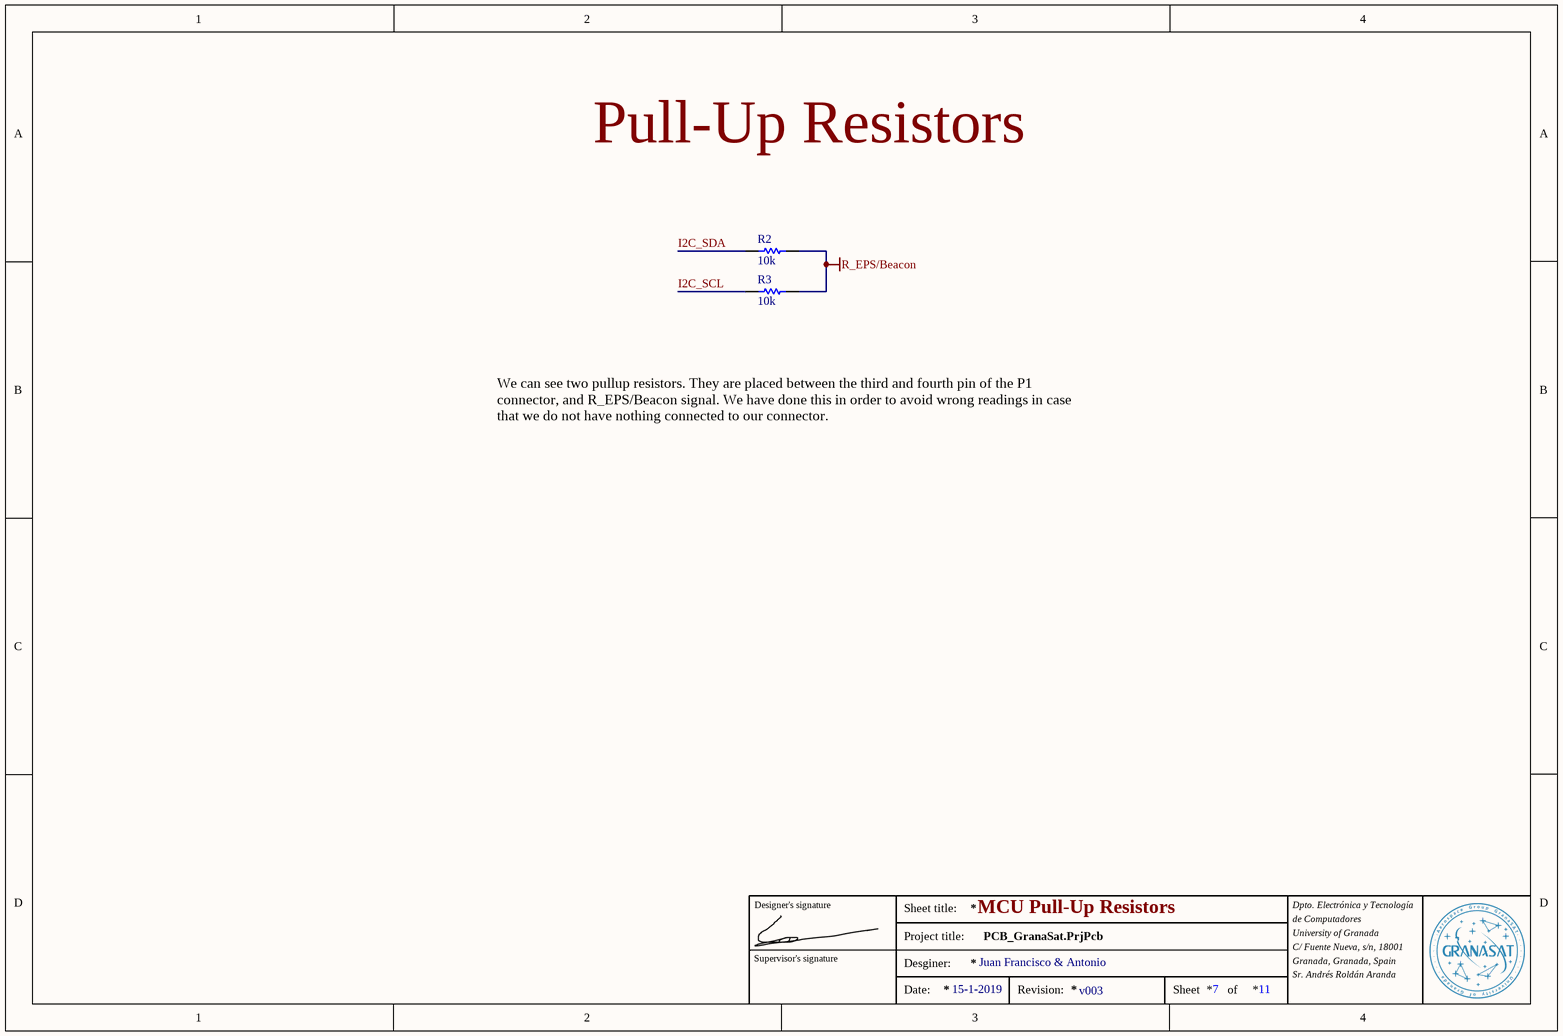
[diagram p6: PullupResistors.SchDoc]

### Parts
R2  10k  [R10k]
R3  10k  [R10k]

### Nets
R_EPS/Beacon: R2.2 R3.2
I2C_SCL: R3.1
I2C_SDA: R2.1

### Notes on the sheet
- Pull-Up Resistors
- We can see two pullup resistors. They are placed between the third and fourth pin of the P1 connector, and R_EPS/Beacon signal. We have done this in order to avoid wrong readings in case that we do not have nothing connected to our connector.
- Designer's signature
- Sheet title:
- MCU Pull-Up Resistors
- Dpto. Electrónica y Tecnología
- de Computadores
- Supervisor's signature
- Project title:
- Desginer:
- Juan Francisco & Antonio
- University of Granada
- C/ Fuente Nueva, s/n, 18001
- Granada, Granada, Spain
- Sr. Andrés Roldán Aranda
- Date:
- 15-1-2019
- Revision:
- v003
- Sheet
- 7
- of
- 11

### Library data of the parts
R2 R3 = Res1: Resistor

## Sheet Reset.SchDoc
size A4
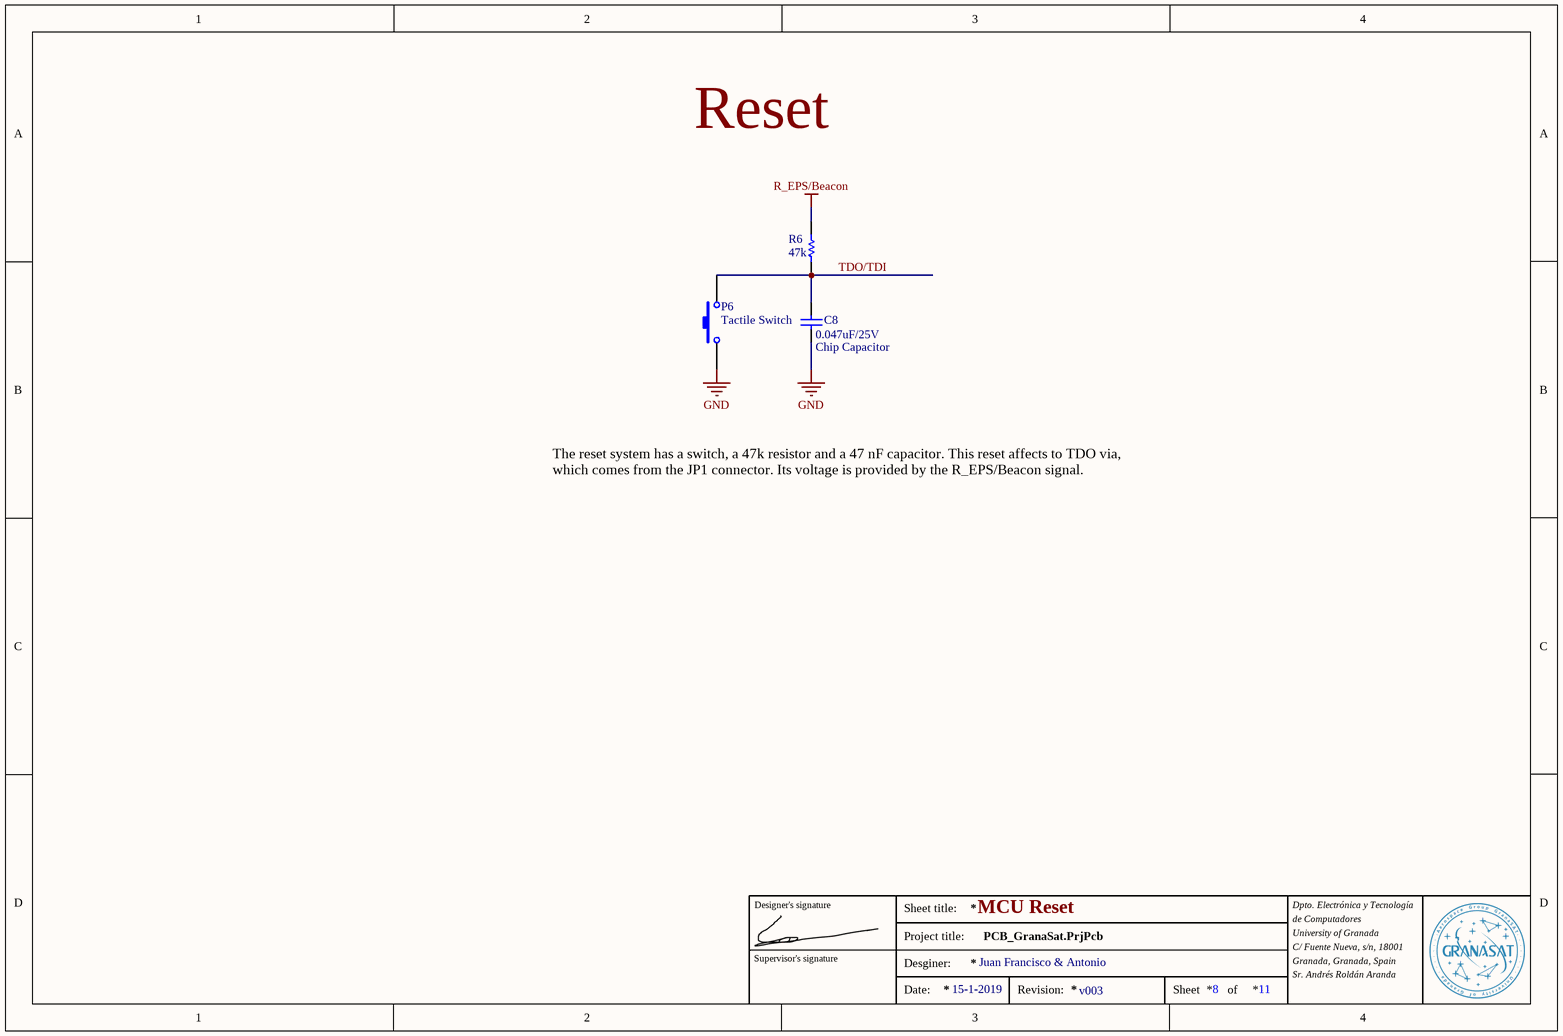
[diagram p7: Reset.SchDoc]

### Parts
C8  value 0.047uF/25V  PackageDescription: Chip Capacitor  [C0.047u]
P6  Tactile Switch  [SPST-2]
R6  47k  [R47k]

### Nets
GND: C8.2 P6.1
R_EPS/Beacon: R6.2
TDO/TDI: C8.1 P6.2 R6.1

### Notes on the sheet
- Reset
- The reset system has a switch, a 47k resistor and a 47 nF capacitor. This reset affects to TDO via, which comes from the JP1 connector. Its voltage is provided by the R_EPS/Beacon signal.
- Designer's signature
- Sheet title:
- MCU Reset
- Dpto. Electrónica y Tecnología
- de Computadores
- Supervisor's signature
- Project title:
- Desginer:
- Juan Francisco & Antonio
- University of Granada
- C/ Fuente Nueva, s/n, 18001
- Granada, Granada, Spain
- Sr. Andrés Roldán Aranda
- Date:
- 15-1-2019
- Revision:
- v003
- Sheet
- 8
- of
- 11

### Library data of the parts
C8 = Cap Semi: Capacitor (Semiconductor SIM Model)
P6 = SW-PB: Switch
R6 = Res1: Resistor

## Sheet LedsSystem.SchDoc
size A4
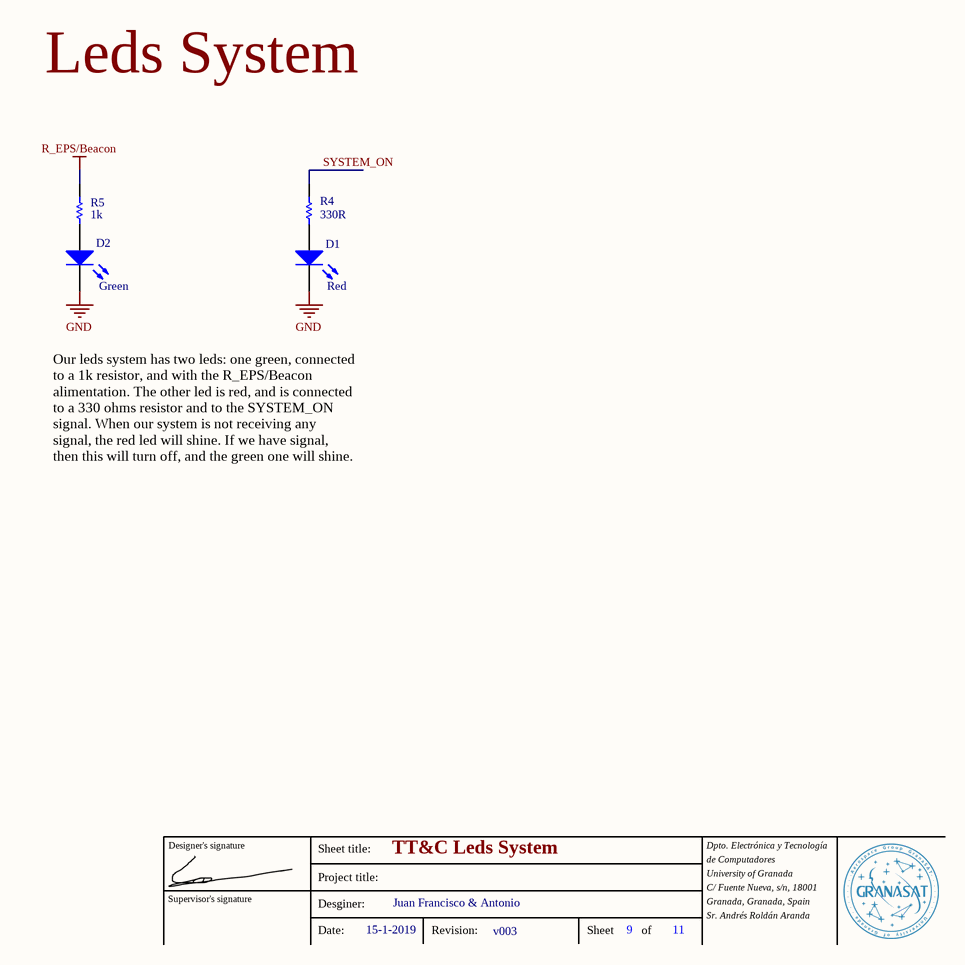
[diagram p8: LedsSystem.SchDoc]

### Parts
D1  Red  [LEDR]
D2  Green  [LEDG]
R4  value 330R  [R330]
R5  1k  [R1k]

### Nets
GND: D1.2(K) D2.2(K)
R_EPS/Beacon: R5.2
SYSTEM_ON: R4.2

Not connected (* = marked no-connect by the designer): D1 1(A); D2 1(A); R4 1; R5 1

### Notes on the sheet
- Leds System
- Our leds system has two leds: one green, connected to a 1k resistor, and with the R_EPS/Beacon alimentation. The other led is red, and is connected to a 330 ohms resistor and to the SYSTEM_ON signal. When our system is not receiving any signal, the red led will shine. If we have signal, then this will turn off, and the green one will shine.
- Designer's signature
- Sheet title:
- TT&C Leds System
- Dpto. Electrónica y Tecnología
- de Computadores
- Supervisor's signature
- Project title:
- Desginer:
- Juan Francisco & Antonio
- University of Granada
- C/ Fuente Nueva, s/n, 18001
- Granada, Granada, Spain
- Sr. Andrés Roldán Aranda
- Date:
- 15-1-2019
- Revision:
- v003
- Sheet
- 9
- of
- 11

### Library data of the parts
D1 D2 = LED2: Typical RED, GREEN, YELLOW, AMBER GaAs LED
R4 R5 = Res1: Resistor

## Sheet Radio_RF4463F30_Beacon.SchDoc
size A4
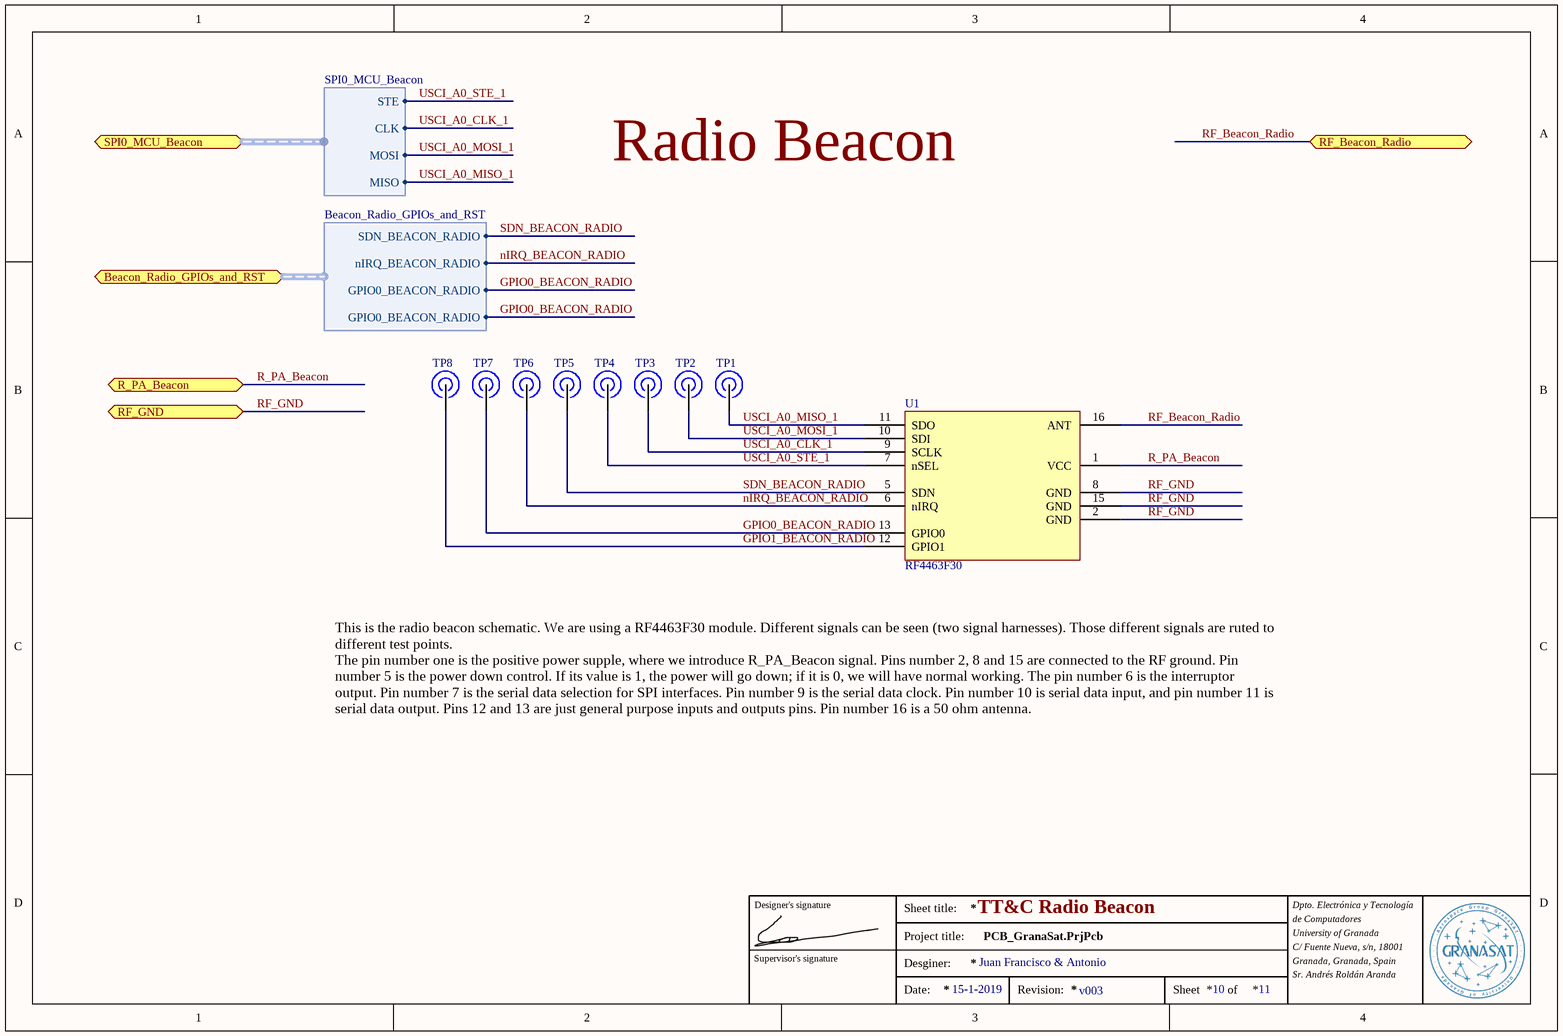
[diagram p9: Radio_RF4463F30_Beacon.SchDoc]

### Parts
TP1  TestPoint  [TESTPOINT_2x2mm]  (value not drawn)
TP2  TestPoint  [TESTPOINT_2x2mm]  (value not drawn)
TP3  TestPoint  [TESTPOINT_2x2mm]  (value not drawn)
TP4  TestPoint  [TESTPOINT_2x2mm]  (value not drawn)
TP5  TestPoint  [TESTPOINT_2x2mm]  (value not drawn)
TP6  TestPoint  [TESTPOINT_2x2mm]  (value not drawn)
TP7  TestPoint  [TESTPOINT_2x2mm]  (value not drawn)
TP8  TestPoint  [TESTPOINT_2x2mm]  (value not drawn)
U1  RF4463F30

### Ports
Beacon_Radio_GPIOs_and_RST (harness Beacon_Radio_GPIOs_and_RST), R_PA_Beacon, RF_Beacon_Radio, RF_GND, SPI0_MCU_Beacon (harness SPI0_MCU_Beacon)

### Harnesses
SPI0_MCU_Beacon: STE, CLK, MOSI, MISO
Beacon_Radio_GPIOs_and_RST: SDN_BEACON_RADIO, nIRQ_BEACON_RADIO, GPIO0_BEACON_RADIO, GPIO0_BEACON_RADIO

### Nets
GPIO0_BEACON_RADIO: TP7.1 U1.13(GPIO0) ; port Beacon_Radio_GPIOs_and_RST.GPIO0_BEACON_RADIO
GPIO1_BEACON_RADIO: TP8.1 U1.12(GPIO1)
nIRQ_BEACON_RADIO: TP6.1 U1.6(nIRQ) ; port Beacon_Radio_GPIOs_and_RST.nIRQ_BEACON_RADIO
R_PA_Beacon: U1.1(VCC) ; port R_PA_Beacon
RF_Beacon_Radio: U1.16(ANT) ; port RF_Beacon_Radio
RF_GND: U1.2(GND) U1.8(GND) U1.15(GND) ; port RF_GND
SDN_BEACON_RADIO: TP5.1 U1.5(SDN) ; port Beacon_Radio_GPIOs_and_RST.SDN_BEACON_RADIO
USCI_A0_CLK_1: TP3.1 U1.9(SCLK) ; port SPI0_MCU_Beacon.CLK
USCI_A0_MISO_1: TP1.1 U1.11(SDO) ; port SPI0_MCU_Beacon.MISO
USCI_A0_MOSI_1: TP2.1 U1.10(SDI) ; port SPI0_MCU_Beacon.MOSI
USCI_A0_STE_1: TP4.1 U1.7(nSEL) ; port SPI0_MCU_Beacon.STE

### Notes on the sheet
- Radio Beacon
- This is the radio beacon schematic. We are using a RF4463F30 module. Different signals can be seen (two signal harnesses). Those different signals are ruted to different test points.
  The pin number one is the positive power supple, where we introduce R_PA_Beacon signal. Pins number 2, 8 and 15 are connected to the RF ground. Pin number 5 is the power down control. If its value is 1, the power will go down; if it is 0, we will have normal working. The pin number 6 is the interruptor output. Pin number 7 is the serial data selection for SPI interfaces. Pin number 9 is the serial data clock. Pin number 10 is serial data input, and pin number 11 is serial data output. Pins 12 and 13 are just general purpose inputs and outputs pins. Pin number 16 is a 50 ohm antenna.
- Designer's signature
- Sheet title:
- TT&C Radio Beacon
- Dpto. Electrónica y Tecnología
- de Computadores
- Supervisor's signature
- Project title:
- Desginer:
- Juan Francisco & Antonio
- University of Granada
- C/ Fuente Nueva, s/n, 18001
- Granada, Granada, Spain
- Sr. Andrés Roldán Aranda
- Date:
- 15-1-2019
- Revision:
- v003
- Sheet
- 10
- of
- 11

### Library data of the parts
TP1-TP8 = TestPoint: Punto de prueba de 3x3mm; pin to pad: 1>TP; PCB DECAL: TestPoint XxXmm

## Sheet Radio_RF4463F30_Transceiver.SchDoc
size A4
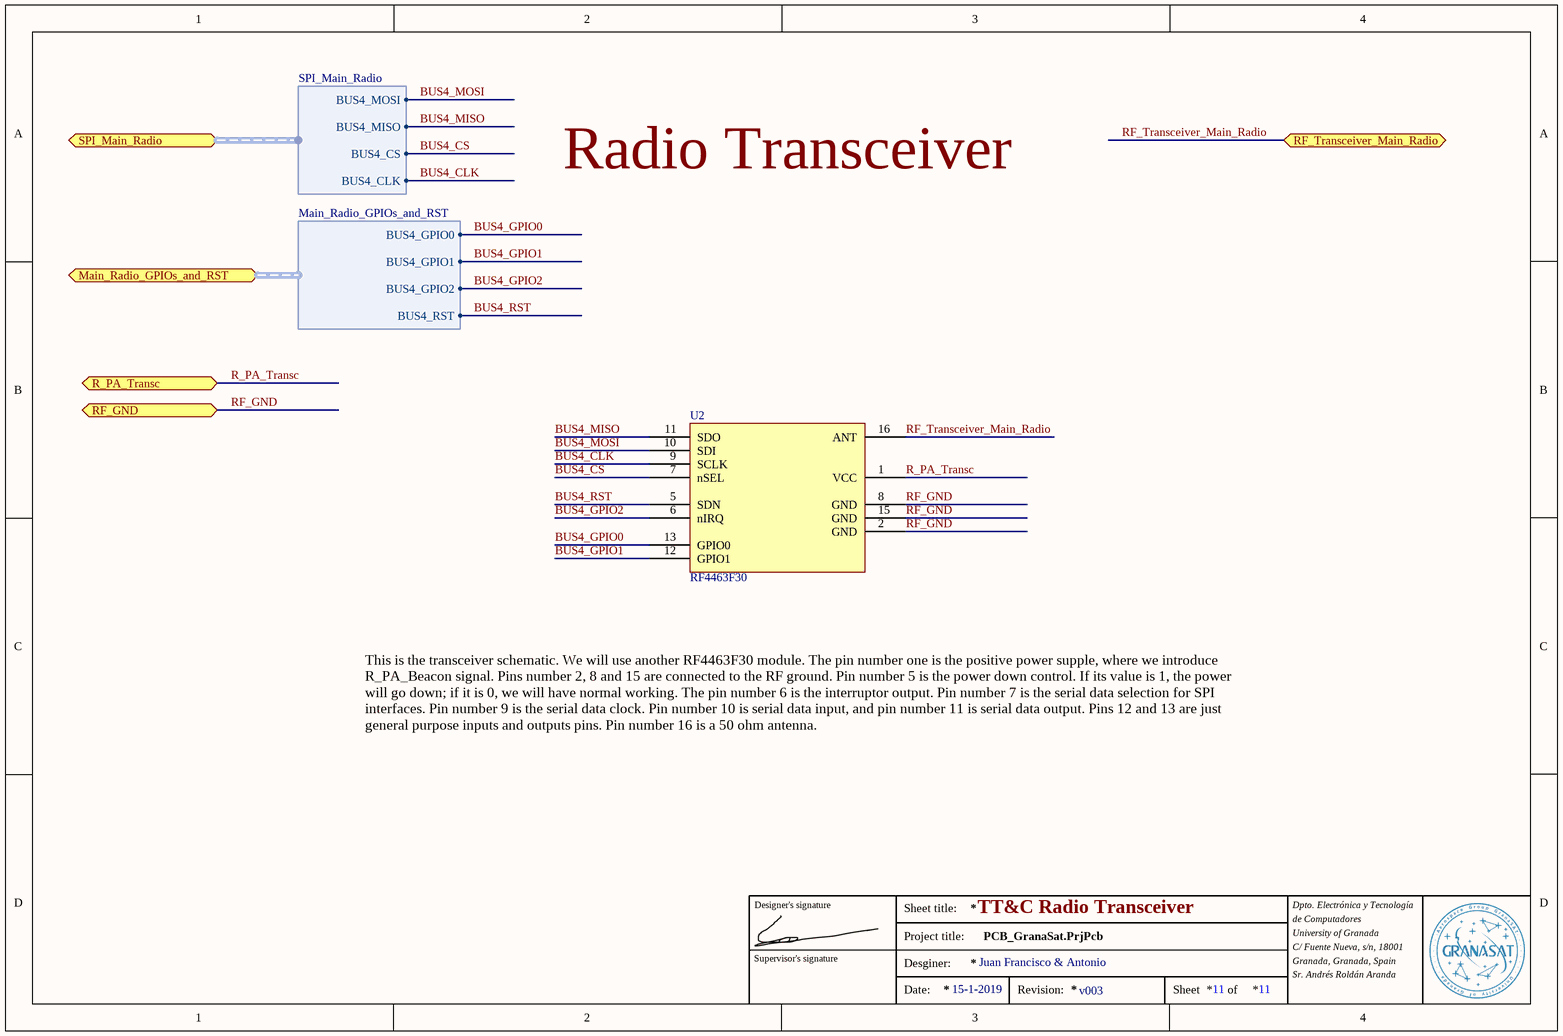
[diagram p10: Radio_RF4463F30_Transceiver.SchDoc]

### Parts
U2  RF4463F30

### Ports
Main_Radio_GPIOs_and_RST (harness Main_Radio_GPIOs_and_RST), R_PA_Transc, RF_GND, RF_Transceiver_Main_Radio, SPI_Main_Radio (harness SPI_Main_Radio)

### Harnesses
SPI_Main_Radio: BUS4_MOSI, BUS4_MISO, BUS4_CS, BUS4_CLK
Main_Radio_GPIOs_and_RST: BUS4_GPIO0, BUS4_GPIO1, BUS4_GPIO2, BUS4_RST

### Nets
BUS4_CLK: U2.9(SCLK) ; port SPI_Main_Radio.BUS4_CLK
BUS4_CS: U2.7(nSEL) ; port SPI_Main_Radio.BUS4_CS
BUS4_GPIO0: U2.13(GPIO0) ; port Main_Radio_GPIOs_and_RST.BUS4_GPIO0
BUS4_GPIO1: U2.12(GPIO1) ; port Main_Radio_GPIOs_and_RST.BUS4_GPIO1
BUS4_GPIO2: U2.6(nIRQ) ; port Main_Radio_GPIOs_and_RST.BUS4_GPIO2
BUS4_MISO: U2.11(SDO) ; port SPI_Main_Radio.BUS4_MISO
BUS4_MOSI: U2.10(SDI) ; port SPI_Main_Radio.BUS4_MOSI
BUS4_RST: U2.5(SDN) ; port Main_Radio_GPIOs_and_RST.BUS4_RST
R_PA_Transc: U2.1(VCC) ; port R_PA_Transc
RF_GND: U2.2(GND) U2.8(GND) U2.15(GND) ; port RF_GND
RF_Transceiver_Main_Radio: U2.16(ANT) ; port RF_Transceiver_Main_Radio

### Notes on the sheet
- Radio Transceiver
- This is the transceiver schematic. We will use another RF4463F30 module. The pin number one is the positive power supple, where we introduce R_PA_Beacon signal. Pins number 2, 8 and 15 are connected to the RF ground. Pin number 5 is the power down control. If its value is 1, the power will go down; if it is 0, we will have normal working. The pin number 6 is the interruptor output. Pin number 7 is the serial data selection for SPI interfaces. Pin number 9 is the serial data clock. Pin number 10 is serial data input, and pin number 11 is serial data output. Pins 12 and 13 are just general purpose inputs and outputs pins. Pin number 16 is a 50 ohm antenna.
- Designer's signature
- Sheet title:
- TT&C Radio Transceiver
- Dpto. Electrónica y Tecnología
- de Computadores
- Supervisor's signature
- Project title:
- Desginer:
- Juan Francisco & Antonio
- University of Granada
- C/ Fuente Nueva, s/n, 18001
- Granada, Granada, Spain
- Sr. Andrés Roldán Aranda
- Date:
- 15-1-2019
- Revision:
- v003
- Sheet
- 11
- of

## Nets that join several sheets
GND: Interface (5 pins), BeaconMCU (8 pins), DecouplingCapacitors (10 pins), Reset (C8.2 P6.1), LedsSystem (D1.2 D2.2)
R_EPS/Beacon: BeaconMCU (U4B.11), DecouplingCapacitors (10 pins), PullupResistors (R2.2 R3.2), Reset (R6.2), LedsSystem (R5.2)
